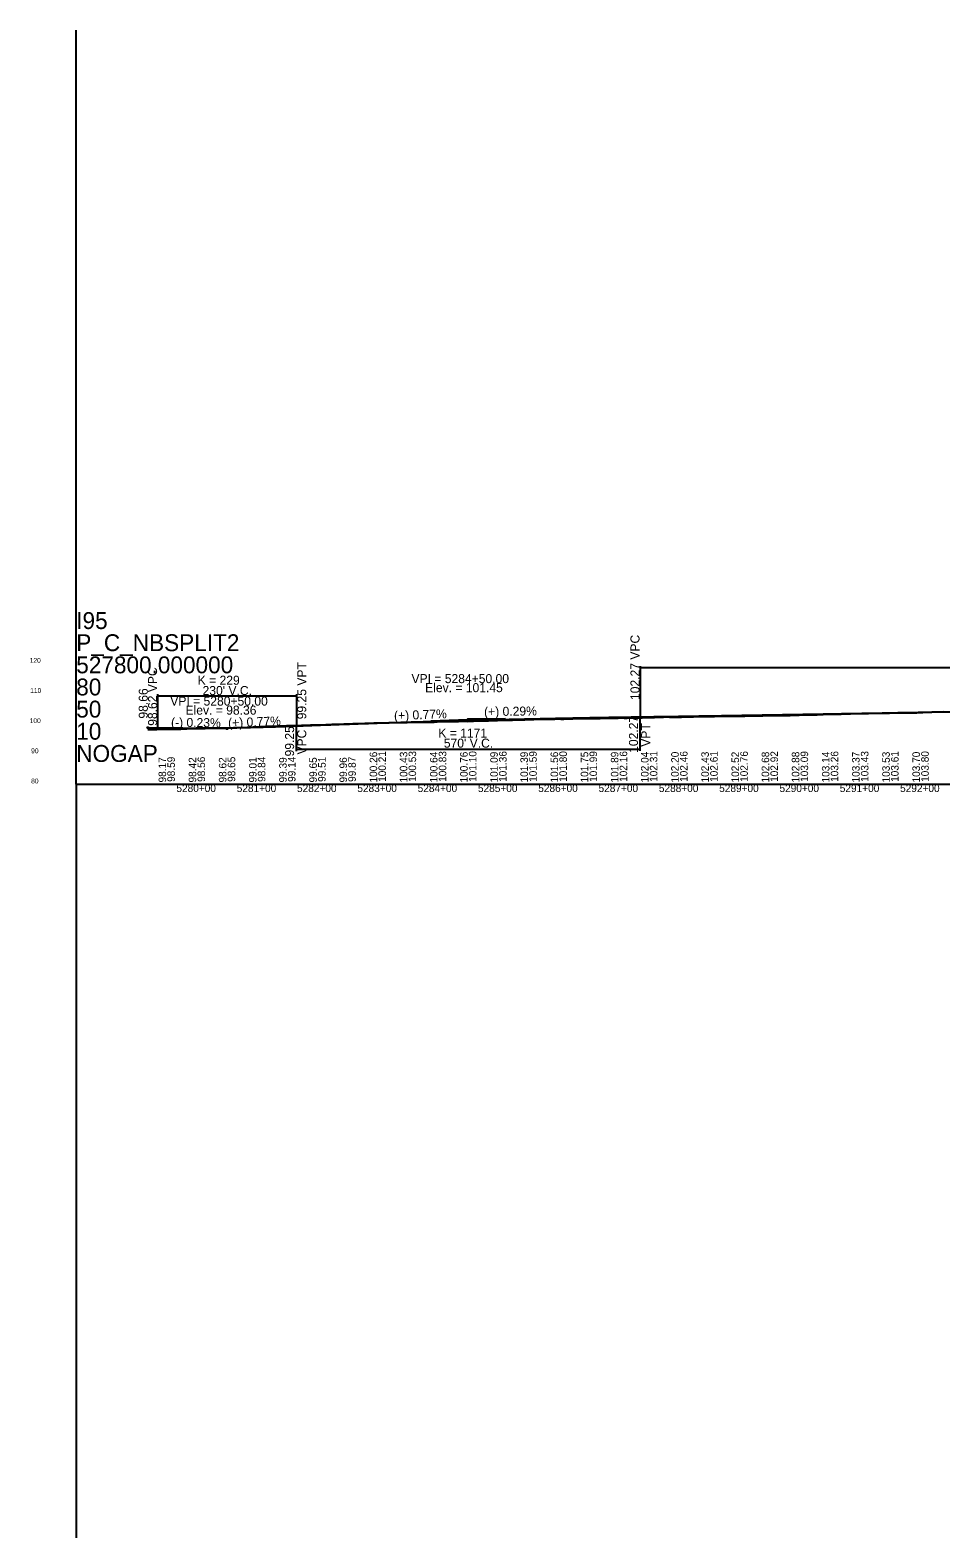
# Model space of a CAD drawing. Extents: x 2121671 to 2169879, y 557274 to 599957.
# Drawn here: x 2157291 to 2158802, y 580937 to 583437 of the extents above; entities that cross this region are included whole.
import ezdxf

# ---------------------------------------------------------------- set-up
doc = ezdxf.new("R2010")
doc.units = 0
for name, color, linetype in [('RD_DDB_ElevTX', 7, 'Continuous'), ('RD_DDB_GradeTX', 7, 'Continuous'), ('RD_DDB_Profile_EX', 7, 'Continuous'), ('RD_DDB_Profile_Lbl', 7, 'Continuous'), ('RD_DDB_Profile_PR', 7, 'Continuous'), ('RD_DDB_StaTX', 7, 'Continuous'), ('RD_DDB_StripGrade', 7, 'Continuous'), ('RD_DDB_VCLbl', 7, 'Continuous'), ('RD_GPK_Profile_Cell', 7, 'Continuous')]:
    doc.layers.add(name, color=color, linetype=linetype)

msp = doc.modelspace()

# ---------------------------------------------------------------- linework, layer by layer
at = {"layer": 'RD_DDB_GradeTX'}
for p, q in [((2157555.9, 582279.3), (2157616.9, 582278.6)), ((2157679.9, 582281), (2157618.9, 582278.7)), ((2157956, 582291.7), (2158016.9, 582294)), ((2158079.9, 582295), (2158018.9, 582294.1))]:
    msp.add_line(p, q, dxfattribs=at)
for centre in [(2157486.5, 582280.1), (2157617.9, 582278.6), (2158017.9, 582294.1)]:
    msp.add_circle(centre, 1, dxfattribs=at)
at = {"layer": 'RD_DDB_Profile_EX'}
for points in [[(2158486.5, 582299.8), (2158491.5, 582299.9), (2158496.5, 582299.9), (2158501.5, 582300), (2158506.5, 582300.1), (2158511.5, 582300.2), (2158516.5, 582300.2), (2158521.5, 582300.3), (2158526.5, 582300.3), (2158531.5, 582300.3), (2158536.5, 582300.3), (2158541.5, 582300.3), (2158546.5, 582300.4), (2158551.5, 582300.6), (2158556.5, 582300.8), (2158561.5, 582301.1), (2158566.5, 582301.2), (2158571.5, 582301.4), (2158576.5, 582301.5), (2158581.5, 582301.7), (2158586.5, 582301.6), (2158591.5, 582301.7), (2158596.5, 582301.7), (2158601.5, 582302), (2158606.5, 582302.3), (2158611.5, 582302.4), (2158616.5, 582302.5), (2158621.5, 582302.6), (2158626.5, 582302.7), (2158631.5, 582302.8), (2158636.5, 582302.9), (2158641.5, 582303), (2158646.5, 582303.1), (2158651.5, 582303.2), (2158656.5, 582303.5), (2158661.5, 582303.6), (2158666.5, 582303.6), (2158671.5, 582303.8), (2158676.5, 582303.9), (2158681.5, 582303.9), (2158686.5, 582304.1), (2158691.5, 582304.2), (2158696.5, 582304.1), (2158701.5, 582304.3), (2158706.5, 582304.4), (2158711.5, 582304.4), (2158716.5, 582304.4), (2158721.5, 582304.6), (2158726.5, 582304.6), (2158731.5, 582304.6), (2158736.5, 582304.7), (2158741.5, 582304.7), (2158746.5, 582304.8), (2158751.5, 582304.9), (2158756.5, 582305), (2158761.5, 582305.1), (2158766.5, 582305.3), (2158771.5, 582305.4), (2158776.5, 582306.2), (2158781.5, 582306.2), (2158786.5, 582306.3), (2158791.5, 582306.4), (2158796.5, 582306.6), (2158801.5, 582306.7), (2158806.5, 582306.8)], [(2157486.5, 582277.3), (2157491.5, 582277.3), (2157496.5, 582277.4), (2157501.5, 582277.4), (2157506.5, 582277.5), (2157511.5, 582277.6), (2157516.5, 582277.7), (2157521.5, 582277.7), (2157526.5, 582277.8), (2157531.5, 582277.9), (2157536.5, 582277.9), (2157541.5, 582278), (2157546.5, 582278.2), (2157551.5, 582278.4), (2157556.5, 582278.6), (2157561.5, 582278.7), (2157566.5, 582278.9), (2157571.5, 582279), (2157576.5, 582279.1), (2157581.5, 582279.1), (2157586.5, 582279.3), (2157591.5, 582279.4), (2157596.5, 582279.5), (2157601.5, 582279.6), (2157606.5, 582279.7), (2157611.5, 582279.8), (2157616.5, 582280), (2157621.5, 582279.8), (2157626.5, 582280.1), (2157631.5, 582280.4), (2157636.5, 582280.5), (2157641.5, 582280.5), (2157646.5, 582280.6), (2157651.5, 582280.9), (2157656.5, 582281.2), (2157661.5, 582281.5), (2157666.5, 582281.8), (2157671.5, 582282.1), (2157676.5, 582282.4), (2157681.5, 582282.5), (2157686.5, 582282.7), (2157691.5, 582282.8), (2157696.5, 582283), (2157701.5, 582283.1), (2157706.5, 582283.2), (2157711.5, 582283.5), (2157716.5, 582283.7), (2157721.5, 582283.9), (2157726.5, 582283.9), (2157731.5, 582284.1), (2157736.5, 582284.1), (2157741.5, 582284.2), (2157746.5, 582284.2), (2157751.5, 582284.6), (2157756.5, 582284.9), (2157761.5, 582284.9), (2157766.5, 582285), (2157771.5, 582285.2), (2157776.5, 582285.2), (2157781.5, 582285.4), (2157786.5, 582285.7), (2157791.5, 582285.8), (2157796.5, 582286), (2157801.5, 582286.2), (2157806.5, 582286.3), (2157811.5, 582286.4), (2157816.5, 582286.6), (2157821.5, 582286.7), (2157826.5, 582287), (2157831.5, 582287.2), (2157836.5, 582287.3), (2157841.5, 582287.4), (2157846.5, 582287.6), (2157851.5, 582287.8), (2157856.5, 582287.9), (2157861.5, 582288), (2157866.5, 582288.1), (2157871.5, 582288.2), (2157876.5, 582288.4), (2157881.5, 582288.5), (2157886.5, 582288.6), (2157891.5, 582288.6), (2157896.5, 582288.6), (2157901.5, 582288.7), (2157906.5, 582288.8), (2157911.5, 582288.9), (2157916.5, 582288.9), (2157921.5, 582289.1), (2157926.5, 582289.2), (2157931.5, 582289.2), (2157936.5, 582289.3), (2157941.5, 582289.5), (2157946.5, 582289.5), (2157951.5, 582289.5), (2157956.5, 582289.5), (2157961.5, 582289.6), (2157966.5, 582289.9), (2157971.5, 582290.3), (2157976.5, 582290.3), (2157981.5, 582290.2), (2157986.5, 582290.4)], [(2157986.5, 582290.4), (2157991.5, 582290.5), (2157996.5, 582290.6), (2158001.5, 582290.7), (2158006.5, 582290.9), (2158011.5, 582290.9), (2158016.5, 582290.4), (2158021.5, 582291.2), (2158026.5, 582291.2), (2158031.5, 582291.3), (2158036.5, 582291.4), (2158041.5, 582291.5), (2158046.5, 582291.7), (2158051.5, 582291.8), (2158056.5, 582291.9), (2158061.5, 582291.9), (2158066.5, 582292.2), (2158071.5, 582292.4), (2158076.5, 582292.6), (2158081.5, 582292.7), (2158086.5, 582292.8), (2158091.5, 582292.9), (2158096.5, 582293.1), (2158101.5, 582293.1), (2158106.5, 582293.1), (2158111.5, 582293.5), (2158116.5, 582293.7), (2158121.5, 582293.9), (2158126.5, 582294), (2158131.5, 582294.1), (2158136.5, 582294.1), (2158141.5, 582294.2), (2158146.5, 582294.3), (2158151.5, 582294.4), (2158156.5, 582294.5), (2158161.5, 582294.6), (2158166.5, 582294.7), (2158171.5, 582294.5), (2158176.5, 582294.6), (2158181.5, 582294.7), (2158186.5, 582294.8), (2158191.5, 582295), (2158196.5, 582295.3), (2158201.5, 582295.4), (2158206.5, 582295.5), (2158211.5, 582295.5), (2158216.5, 582295.6), (2158221.5, 582295.6), (2158226.5, 582295.6), (2158231.5, 582295.5), (2158236.5, 582295.7), (2158241.5, 582295.8), (2158246.5, 582296), (2158251.5, 582296.1), (2158256.5, 582296.1), (2158261.5, 582296.2), (2158266.5, 582296.2), (2158271.5, 582296.3), (2158276.5, 582296.2), (2158281.5, 582296.2), (2158286.5, 582296.3), (2158291.5, 582296.3), (2158296.5, 582296.2), (2158301.5, 582296.6), (2158306.5, 582296.8), (2158311.5, 582296.9), (2158316.5, 582297), (2158321.5, 582297.1), (2158326.5, 582297.3), (2158331.5, 582297.5), (2158336.5, 582297.7), (2158341.5, 582297.8), (2158346.5, 582298), (2158351.5, 582297.9), (2158356.5, 582297.9), (2158361.5, 582297.8), (2158366.5, 582297.8), (2158371.5, 582297.9), (2158376.5, 582298), (2158381.5, 582298.1), (2158386.5, 582298.2), (2158391.5, 582298.3), (2158396.5, 582298.5), (2158401.5, 582298.5), (2158406.5, 582298.5), (2158411.5, 582298.5), (2158416.5, 582299), (2158421.5, 582299), (2158426.5, 582299), (2158431.5, 582299.1), (2158436.5, 582299.1), (2158441.5, 582299.2), (2158446.5, 582299.3), (2158451.5, 582299.4), (2158456.5, 582299.5), (2158461.5, 582299.4), (2158466.5, 582299.4), (2158471.5, 582299.4), (2158476.5, 582299.5), (2158481.5, 582299.7), (2158486.5, 582299.8)]]:
    msp.add_lwpolyline(points, dxfattribs=at)
at = {"layer": 'RD_DDB_Profile_PR'}
msp.add_line((2157486.5, 582280.1), (2157502.9, 582279.9), dxfattribs=at)
for points in [[(2158302.9, 582298.2), (2158332.9, 582298.6), (2158362.9, 582299), (2158392.9, 582299.5), (2158422.9, 582299.9), (2158452.9, 582300.4), (2158482.9, 582300.9), (2158512.9, 582301.4), (2158542.9, 582301.9), (2158572.9, 582302.4), (2158602.9, 582302.9), (2158632.9, 582303.4), (2158662.9, 582303.9), (2158692.9, 582304.4), (2158722.9, 582305), (2158752.9, 582305.5), (2158782.9, 582306.1), (2158812.9, 582306.7), (2158842.9, 582307.2), (2158872.9, 582307.8), (2158902.9, 582308.4), (2158932.9, 582309), (2158962.9, 582309.6), (2158992.9, 582310.2), (2159022.9, 582310.8), (2159052.9, 582311.5), (2159082.9, 582312.1), (2159112.9, 582312.8), (2159142.9, 582313.4), (2159172.9, 582314.1), (2159202.9, 582314.8), (2159232.9, 582315.4), (2159262.9, 582316.1), (2159292.9, 582316.8), (2159322.9, 582317.5), (2159352.9, 582318.2), (2159382.9, 582319), (2159412.9, 582319.7), (2159442.9, 582320.4), (2159472.9, 582321.2), (2159502.9, 582321.9), (2159532.9, 582322.7), (2159562.9, 582323.5), (2159592.9, 582324.3), (2159622.9, 582325), (2159652.9, 582325.8), (2159682.9, 582326.6), (2159712.9, 582327.5), (2159742.9, 582328.3), (2159772.9, 582329.1), (2159802.9, 582329.9)], [(2157502.9, 582279.9), (2157507.5, 582279.9), (2157512.1, 582279.8), (2157516.7, 582279.8), (2157521.3, 582279.8), (2157525.9, 582279.7), (2157530.5, 582279.7), (2157535.1, 582279.7), (2157539.7, 582279.7), (2157544.3, 582279.7), (2157548.9, 582279.6), (2157553.5, 582279.6), (2157558.1, 582279.6), (2157562.7, 582279.6), (2157567.3, 582279.7), (2157571.9, 582279.7), (2157576.5, 582279.7), (2157581.1, 582279.7), (2157585.7, 582279.7), (2157590.3, 582279.8), (2157594.9, 582279.8), (2157599.5, 582279.8), (2157604.1, 582279.9), (2157608.7, 582279.9), (2157613.3, 582280), (2157617.9, 582280.1), (2157622.5, 582280.1), (2157627.1, 582280.2), (2157631.7, 582280.3), (2157636.3, 582280.3), (2157640.9, 582280.4), (2157645.5, 582280.5), (2157650.1, 582280.6), (2157654.7, 582280.7), (2157659.3, 582280.8), (2157663.9, 582280.9), (2157668.5, 582281), (2157673.1, 582281.1), (2157677.7, 582281.3), (2157682.3, 582281.4), (2157686.9, 582281.5), (2157691.5, 582281.6), (2157696.1, 582281.8), (2157700.7, 582281.9), (2157705.3, 582282.1), (2157709.9, 582282.2), (2157714.5, 582282.4), (2157719.1, 582282.6), (2157723.7, 582282.7), (2157728.3, 582282.9), (2157732.9, 582283.1)], [(2157732.9, 582283.1), (2157744.3, 582283.5), (2157755.7, 582283.9), (2157767.1, 582284.4), (2157778.5, 582284.8), (2157789.9, 582285.2), (2157801.3, 582285.6), (2157812.7, 582286), (2157824.1, 582286.4), (2157835.5, 582286.8), (2157846.9, 582287.2), (2157858.3, 582287.6), (2157869.7, 582288), (2157881.1, 582288.3), (2157892.5, 582288.7), (2157903.9, 582289), (2157915.3, 582289.4), (2157926.7, 582289.8), (2157938.1, 582290.1), (2157949.5, 582290.4), (2157960.9, 582290.8), (2157972.3, 582291.1), (2157983.7, 582291.4), (2157995.1, 582291.7), (2158006.5, 582292), (2158017.9, 582292.3), (2158029.3, 582292.6), (2158040.7, 582292.9), (2158052.1, 582293.2), (2158063.5, 582293.5), (2158074.9, 582293.8), (2158086.3, 582294.1), (2158097.7, 582294.3), (2158109.1, 582294.6), (2158120.5, 582294.8), (2158131.9, 582295.1), (2158143.3, 582295.3), (2158154.7, 582295.6), (2158166.1, 582295.8), (2158177.5, 582296), (2158188.9, 582296.2), (2158200.3, 582296.5), (2158211.7, 582296.7), (2158223.1, 582296.9), (2158234.5, 582297.1), (2158245.9, 582297.3), (2158257.3, 582297.5), (2158268.7, 582297.6), (2158280.1, 582297.8), (2158291.5, 582298), (2158302.9, 582298.2)]]:
    msp.add_spline(points, degree=3, dxfattribs=at)
at = {"layer": 'RD_DDB_VCLbl'}
for p, q in [((2158302.9, 582382.4), (2158302.9, 582298.2)), ((2158302.9, 582379.9), (2159802.9, 582379.9)), ((2157502.9, 582335.6), (2157502.9, 582279.9)), ((2157502.9, 582333.1), (2157732.9, 582333.1)), ((2157732.9, 582335.6), (2157732.9, 582283.1)), ((2157732.9, 582241), (2157732.9, 582283.1)), ((2158302.9, 582242.1), (2158302.9, 582298.2)), ((2157732.9, 582244.8), (2158302.9, 582244.8))]:
    msp.add_line(p, q, dxfattribs=at)
at = {"layer": 'RD_GPK_Profile_Cell'}
for q in [(2157367.9, 583436.8), (2160167.9, 582186.8), (2157367.9, 580936.8)]:
    msp.add_line((2157367.9, 582186.8), q, dxfattribs=at)

# ---------------------------------------------------------------- texts
at = {"layer": 'RD_DDB_ElevTX'}
for s, p in [('120', (2157290.7, 582387.8)), ('110', (2157291.5, 582337.8)), ('100', (2157290.7, 582287.8)), ('90', (2157293.1, 582237.8)), ('80', (2157293.1, 582187.8))]:
    msp.add_text(s, height=8, dxfattribs=at).set_placement(p)
at = {"layer": 'RD_DDB_GradeTX'}
for s, rotation, p in [('(+) 0.77%', 2.2135, (2157895.1, 582292.6)), ('(+) 0.29%', 0.8206, (2158044.3, 582299.3)), ('(-) 0.23%', 359.3411, (2157525, 582281.7)), ('(+) 0.77%', 2.2135, (2157620, 582280.7))]:
    msp.add_text(s, height=15, rotation=rotation, dxfattribs=at).set_placement(p)
at = {"layer": 'RD_DDB_Profile_Lbl'}
for s, p in [('VPI = 5284+50.00', (2157923.8, 582354.1)), ('Elev. = 101.45', (2157946.4, 582339.1)), ('VPI = 5280+50.00', (2157523.8, 582316.8)), ('Elev. = 98.36', (2157549.1, 582301.8))]:
    msp.add_text(s, height=15, dxfattribs=at).set_placement(p)
msp.add_text('98.66', height=15, rotation=90, dxfattribs=at).set_placement((2157486.5, 582295.3))
at = {"layer": 'RD_DDB_StaTX'}
for s, p in [('5280+00', (2157534, 582173.5)), ('5281+00', (2157634, 582173.5)), ('5282+00', (2157734, 582173.5)), ('5283+00', (2157834, 582173.5)), ('5284+00', (2157934, 582173.5)), ('5285+00', (2158034, 582173.5)), ('5286+00', (2158134, 582173.5)), ('5287+00', (2158234, 582173.5)), ('5288+00', (2158334, 582173.5)), ('5289+00', (2158434, 582173.5)), ('5290+00', (2158534, 582173.5)), ('5291+00', (2158634, 582173.5)), ('5292+00', (2158734, 582173.5))]:
    msp.add_text(s, height=12.5, dxfattribs=at).set_placement(p)
at = {"layer": 'RD_DDB_StripGrade'}
for s, height, p in [('102.27 VPC', 15, (2158301.9, 582326.1)), ('98.62 VPC', 15, (2157501.9, 582283.3)), ('99.25 VPT', 15, (2157749.3, 582294.1)), ('99.25 ', 15, (2157729.1, 582232.5)), ('VPC', 15, (2157749.3, 582235.7)), ('102.27 ', 15, (2158299.4, 582238.5)), ('VPT', 15, (2158319.6, 582248.6)), ('98.17', 12.5, (2157516.9, 582189.3)), ('98.59', 12.5, (2157531.5, 582190.3)), ('98.42', 12.5, (2157566.9, 582189.3)), ('98.56', 12.5, (2157581.5, 582190.3)), ('98.62', 12.5, (2157616.9, 582189.3)), ('98.65', 12.5, (2157631.5, 582190.3)), ('99.01', 12.5, (2157666.9, 582189.3)), ('98.84', 12.5, (2157681.5, 582190.3)), ('99.39', 12.5, (2157716.9, 582189.3)), ('99.14', 12.5, (2157731.5, 582190.3)), ('99.65', 12.5, (2157766.9, 582189.3)), ('99.51', 12.5, (2157781.5, 582190.3)), ('99.96', 12.5, (2157816.9, 582189.3)), ('99.87', 12.5, (2157831.5, 582190.3)), ('100.26', 12.5, (2157866.9, 582189.3)), ('100.21', 12.5, (2157881.5, 582190.3)), ('100.43', 12.5, (2157916.9, 582189.3)), ('100.53', 12.5, (2157931.5, 582190.3)), ('100.64', 12.5, (2157966.9, 582189.3)), ('100.83', 12.5, (2157981.5, 582190.3)), ('100.76', 12.5, (2158016.9, 582189.3)), ('101.10', 12.5, (2158031.5, 582190.3)), ('101.09', 12.5, (2158066.9, 582189.3)), ('101.36', 12.5, (2158081.5, 582190.3)), ('101.39', 12.5, (2158116.9, 582189.3)), ('101.59', 12.5, (2158131.5, 582190.3)), ('101.56', 12.5, (2158166.9, 582189.3)), ('101.80', 12.5, (2158181.5, 582190.3)), ('101.75', 12.5, (2158216.9, 582189.3)), ('101.99', 12.5, (2158231.5, 582190.3)), ('101.89', 12.5, (2158266.9, 582189.3)), ('102.16', 12.5, (2158281.5, 582190.3)), ('102.04', 12.5, (2158316.9, 582189.3)), ('102.31', 12.5, (2158331.5, 582190.3)), ('102.20', 12.5, (2158366.9, 582189.3)), ('102.46', 12.5, (2158381.5, 582190.3)), ('102.43', 12.5, (2158416.9, 582189.3)), ('102.61', 12.5, (2158431.5, 582190.3)), ('102.52', 12.5, (2158466.9, 582189.3)), ('102.76', 12.5, (2158481.5, 582190.3)), ('102.68', 12.5, (2158516.9, 582189.3)), ('102.92', 12.5, (2158531.5, 582190.3)), ('102.88', 12.5, (2158566.9, 582189.3)), ('103.09', 12.5, (2158581.5, 582190.3)), ('103.14', 12.5, (2158616.9, 582189.3)), ('103.26', 12.5, (2158631.5, 582190.3)), ('103.37', 12.5, (2158666.9, 582189.3)), ('103.43', 12.5, (2158681.5, 582190.3)), ('103.53', 12.5, (2158716.9, 582189.3)), ('103.61', 12.5, (2158731.5, 582190.3)), ('103.70', 12.5, (2158766.9, 582189.3)), ('103.80', 12.5, (2158781.5, 582190.3))]:
    msp.add_text(s, height=height, rotation=90, dxfattribs=at).set_placement(p)
at = {"layer": 'RD_DDB_VCLbl'}
for s, p in [('K = 229', (2157569.3, 582351.4)), ("230' V.C.", (2157577.4, 582334.3)), ('K = 1171', (2157968.3, 582263.8)), ("570' V.C.", (2157977.4, 582247.1))]:
    msp.add_text(s, height=15, dxfattribs=at).set_placement(p)
at = {"layer": 'RD_GPK_Profile_Cell'}
for s, p in [('I95', (2157367.9, 582443.8)), ('P_C_NBSPLIT2', (2157367.9, 582407.1)), ('527800.000000', (2157367.9, 582370.4)), ('80', (2157367.9, 582333.7)), ('50', (2157367.9, 582297)), ('10', (2157367.9, 582260.3)), ('NOGAP', (2157367.9, 582223.5))]:
    msp.add_text(s, height=28, dxfattribs=at).set_placement(p)

doc.saveas('drawing.dxf')
